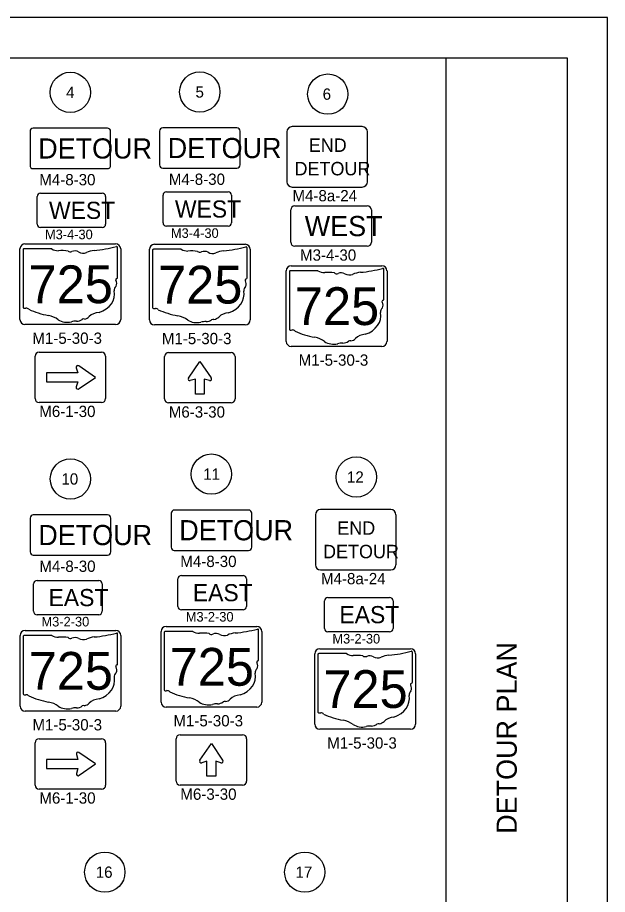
# Model space of a CAD drawing. Extents: x 1341221 to 1914484, y 79347 to 658398.
# Drawn here: x 1461287 to 1494221, y 609451 to 658398 of the extents above; entities that cross this region are included whole.
import ezdxf

# ---------------------------------------------------------------- set-up
doc = ezdxf.new("R2010")
doc.units = 0
for name, color, linetype in [('GM_X_County', 7, 'Continuous'), ('GM_X_County_Road_Text', 7, 'Continuous'), ('GM_X_Minor_Lake', 7, 'Continuous'), ('GM_X_Minor_Lake_Text', 7, 'Continuous'), ('GM_X_Minor_River', 7, 'Continuous'), ('GM_X_Minor_River_Text', 7, 'Continuous')]:
    doc.layers.add(name, color=color, linetype=linetype)

msp = doc.modelspace()

# ---------------------------------------------------------------- linework, layer by layer
at = {"layer": 'GM_X_County'}
for centre in [(1464234, 654220), (1471463, 654244), (1478606, 654124), (1472109, 632912), (1480199, 632751), (1464239, 632642)]:
    msp.add_circle(centre, 1125, dxfattribs=at)
at = {"layer": 'GM_X_County_Road_Text'}
for centre in [(1466159, 610695), (1477321, 610695)]:
    msp.add_circle(centre, 1125, dxfattribs=at)
at = {"layer": 'GM_X_Minor_Lake_Text'}
msp.add_line((1485221, 561648), (1485221, 656148), dxfattribs=at)
msp.add_lwpolyline([(1347971, 656148), (1491971, 656148), (1491971, 561648), (1347971, 561648)], close=True, dxfattribs=at)
at = {"layer": 'GM_X_Minor_River'}
for p, q in [((1462571, 648594), (1466014, 648594)), ((1469602, 648667), (1473045, 648667)), ((1469602, 648667), (1473045, 648667)), ((1462380, 646873), (1462380, 648403)), ((1466205, 648403), (1466205, 646873)), ((1469411, 646946), (1469411, 648476)), ((1469411, 646946), (1469411, 648476)), ((1473236, 648476), (1473236, 646946)), ((1473236, 648476), (1473236, 646946)), ((1476540, 645858), (1476540, 647658)), ((1476765, 647883), (1480815, 647883)), ((1481040, 647658), (1481040, 645858)), ((1466014, 646682), (1462571, 646682)), ((1473045, 646754), (1469602, 646754)), ((1473045, 646754), (1469602, 646754)), ((1480815, 645633), (1476765, 645633)), ((1461597, 645431), (1461597, 642229)), ((1463193, 645486), (1461649, 645486)), ((1466870, 643890), (1466870, 645565)), ((1468827, 645411), (1468827, 642209)), ((1470423, 645466), (1468879, 645466)), ((1474100, 643870), (1474100, 645545)), ((1476463, 644210), (1476463, 641008)), ((1478059, 644265), (1476515, 644265)), ((1481737, 642670), (1481737, 644344)), ((1466870, 643891), (1466870, 643890)), ((1474099, 643871), (1474100, 643870)), ((1481736, 642670), (1481737, 642670)), ((1462265, 637131), (1462265, 639493)), ((1462490, 639718), (1465978, 639718)), ((1466203, 639493), (1466203, 637131)), ((1469495, 637110), (1469495, 639473)), ((1469720, 639698), (1473207, 639698)), ((1473432, 639473), (1473432, 637110)), ((1464566, 638847), (1464656, 638558)), ((1465640, 638312), (1464709, 638952)), ((1470824, 638274), (1471463, 639206)), ((1471463, 639206), (1472092, 638288)), ((1464656, 638558), (1462898, 638558)), ((1462898, 638558), (1462898, 638066)), ((1464722, 637683), (1465640, 638312)), ((1462898, 638066), (1464656, 638066)), ((1464656, 638066), (1464566, 637777)), ((1471217, 638221), (1470929, 638132)), ((1471217, 637377), (1471217, 638221)), ((1471998, 638132), (1471709, 638221)), ((1471709, 638221), (1471709, 637377)), ((1471709, 637377), (1471217, 637377)), ((1465978, 636906), (1462490, 636906)), ((1473207, 636885), (1469720, 636885)), ((1470241, 625531), (1470241, 627061)), ((1470432, 627252), (1473874, 627252)), ((1474066, 627061), (1474066, 625531)), ((1462185, 625258), (1462185, 626788)), ((1462376, 626979), (1465819, 626979)), ((1466010, 626788), (1466010, 625258)), ((1478424, 624305), (1478424, 625835)), ((1478616, 626026), (1482058, 626026)), ((1482249, 625835), (1482249, 624305)), ((1465819, 625066), (1462376, 625066)), ((1473874, 625340), (1470432, 625340)), ((1471069, 624134), (1469524, 624134)), ((1474746, 622538), (1474746, 624213)), ((1482058, 624114), (1478616, 624114)), ((1461602, 623853), (1461602, 620651)), ((1463198, 623908), (1461654, 623908)), ((1466875, 622313), (1466875, 623988)), ((1469472, 624079), (1469472, 620877)), ((1478056, 622837), (1478056, 619635)), ((1479652, 622892), (1478108, 622892)), ((1483330, 621296), (1483330, 622971)), ((1466875, 622313), (1466875, 622313)), ((1474745, 622538), (1474746, 622538)), ((1483329, 621297), (1483330, 621296)), ((1470365, 618366), (1473853, 618366)), ((1462270, 615553), (1462270, 617916)), ((1462495, 618141), (1465982, 618141)), ((1466207, 617916), (1466207, 615553)), ((1470140, 615778), (1470140, 618141)), ((1471469, 616942), (1472109, 617874)), ((1472109, 617874), (1472738, 616956)), ((1474078, 618141), (1474078, 615778)), ((1464571, 617269), (1464660, 616980)), ((1465645, 616734), (1464714, 617374)), ((1464660, 616980), (1462903, 616980)), ((1462903, 616980), (1462903, 616488)), ((1471863, 616889), (1471574, 616800)), ((1471863, 616045), (1471863, 616889)), ((1472644, 616800), (1472355, 616889)), ((1472355, 616889), (1472355, 616045)), ((1462903, 616488), (1464660, 616488)), ((1464660, 616488), (1464571, 616200)), ((1464727, 616106), (1465645, 616734)), ((1472355, 616045), (1471863, 616045)), ((1465982, 615328), (1462495, 615328)), ((1473853, 615553), (1470365, 615553))]:
    msp.add_line(p, q, dxfattribs=at)
for points in [[(1461984, 652035), (1461984, 650145)], [(1466304, 652215), (1462164, 652215)], [(1466484, 650145), (1466484, 652035)], [(1469213, 652060), (1469213, 650170)], [(1473533, 652240), (1469393, 652240)], [(1473713, 650170), (1473713, 652060)], [(1476323, 652018), (1476323, 649228)], [(1480530, 652310), (1476615, 652310)], [(1480823, 649228), (1480823, 652018)], [(1462164, 649965), (1466304, 649965)], [(1469393, 649990), (1473533, 649990)], [(1476615, 648935), (1480530, 648935)], [(1461703, 645762), (1466765, 645762)], [(1468932, 645742), (1473995, 645742)], [(1461421, 641543), (1461421, 645481)], [(1467046, 645481), (1467046, 641543)], [(1468651, 641523), (1468651, 645461)], [(1474276, 645461), (1474276, 641523)], [(1476288, 640322), (1476288, 644260)], [(1476569, 644541), (1481631, 644541)], [(1481913, 644260), (1481913, 640322)], [(1466765, 641262), (1461703, 641262)], [(1473995, 641242), (1468932, 641242)], [(1481631, 640041), (1476569, 640041)], [(1482123, 630937), (1478208, 630937)], [(1461989, 630458), (1461989, 628568)], [(1466309, 630638), (1462169, 630638)], [(1466489, 628568), (1466489, 630458)], [(1469859, 630727), (1469859, 628837)], [(1474179, 630907), (1470039, 630907)], [(1474359, 628837), (1474359, 630727)], [(1477916, 630645), (1477916, 627855)], [(1482416, 627855), (1482416, 630645)], [(1470039, 628657), (1474179, 628657)], [(1462169, 628388), (1466309, 628388)], [(1478208, 627562), (1482123, 627562)], [(1461707, 624184), (1466770, 624184)], [(1469297, 620191), (1469297, 624128)], [(1469578, 624410), (1474640, 624410)], [(1474922, 624128), (1474922, 620191)], [(1461426, 619966), (1461426, 623903)], [(1467051, 623903), (1467051, 619966)], [(1478162, 623168), (1483224, 623168)], [(1477881, 618949), (1477881, 622887)], [(1483506, 622887), (1483506, 618949)], [(1466770, 619684), (1461707, 619684)], [(1474640, 619910), (1469578, 619910)], [(1483224, 618668), (1478162, 618668)]]:
    msp.add_lwpolyline(points, dxfattribs=at)
for centre, radius, start, end in [((1462164, 652035), 180, 90, 180), ((1466304, 652035), 180, 0, 90), ((1469393, 652060), 180, 90, 180), ((1473533, 652060), 180, 0, 90), ((1476615, 652018), 292, 90, 180), ((1480530, 652018), 292, 0, 90), ((1462164, 650145), 180, 180, 270), ((1466304, 650145), 180, 270, 0), ((1469393, 650170), 180, 180, 270), ((1473533, 650170), 180, 270, 0), ((1476615, 649228), 292, 180, 270), ((1480530, 649228), 292, 270, 0), ((1462571, 648403), 191, 90, 180), ((1466014, 648403), 191, 0, 90), ((1469602, 648476), 191, 90, 180), ((1469602, 648476), 191, 90, 180), ((1473045, 648476), 191, 0, 90), ((1473045, 648476), 191, 0, 90), ((1476765, 647658), 225, 90, 180), ((1480815, 647658), 225, 0, 90), ((1462571, 646873), 191, 180, 270), ((1466014, 646873), 191, 270, 0), ((1469602, 646946), 191, 180, 270), ((1469602, 646946), 191, 180, 270), ((1473045, 646946), 191, 270, 0), ((1473045, 646946), 191, 270, 0), ((1461703, 645481), 281, 90, 180), ((1466765, 645481), 281, 0, 90), ((1468932, 645461), 281, 90, 180), ((1473995, 645461), 281, 0, 90), ((1476765, 645858), 225, 180, 270), ((1480815, 645858), 225, 270, 0), ((1476569, 644260), 281, 90, 180), ((1481631, 644260), 281, 0, 90), ((1461703, 641543), 281, 180, 270), ((1466765, 641543), 281, 270, 0), ((1468932, 641523), 281, 180, 270), ((1473995, 641523), 281, 270, 0), ((1476569, 640322), 281, 180, 270), ((1481631, 640322), 281, 270, 0), ((1462490, 639494), 225, 90, 180), ((1465978, 639494), 225, 0, 90), ((1469720, 639473), 225, 90, 180), ((1473207, 639473), 225, 0, 90), ((1464656, 638875), 93.8, 55.4112, 197.2046), ((1470901, 638221), 93.8, 145.4112, 287.2046), ((1472026, 638221), 93.8, 252.7954, 45.0096), ((1464656, 637750), 93.8, 162.7954, 315.0096), ((1462490, 637131), 225, 180, 270), ((1465978, 637131), 225, 270, 360), ((1469720, 637111), 225, 180, 270), ((1473207, 637111), 225, 270, 0), ((1478208, 630645), 292, 90, 180), ((1482123, 630645), 292, 0, 90), ((1462169, 630458), 180, 90, 180), ((1466309, 630458), 180, 0, 90), ((1470039, 630727), 180, 90, 180), ((1474179, 630727), 180, 0, 90), ((1462169, 628568), 180, 180, 270), ((1466309, 628568), 180, 270, 0), ((1470039, 628837), 180, 180, 270), ((1474179, 628837), 180, 270, 0), ((1478208, 627855), 292, 180, 270), ((1482123, 627855), 292, 270, 0), ((1470432, 627061), 191, 90, 180), ((1473874, 627061), 191, 0, 90), ((1462376, 626787), 191, 90, 180), ((1465818, 626787), 191, 0, 90), ((1478615, 625835), 191, 90, 180), ((1482058, 625835), 191, 0, 90), ((1462376, 625257), 191, 180, 270), ((1465818, 625257), 191, 270, 0), ((1470432, 625531), 191, 180, 270), ((1473874, 625531), 191, 270, 0), ((1461707, 623903), 281, 90, 180), ((1466770, 623903), 281, 0, 90), ((1469578, 624128), 281, 90, 180), ((1474640, 624128), 281, 0, 90), ((1478615, 624305), 191, 180, 270), ((1482058, 624305), 191, 270, 0), ((1478162, 622887), 281, 90, 180), ((1483224, 622887), 281, 0, 90), ((1469578, 620191), 281, 180, 270), ((1474640, 620191), 281, 270, 0), ((1461707, 619966), 281, 180, 270), ((1466770, 619966), 281, 270, 0), ((1478162, 618949), 281, 180, 270), ((1483224, 618949), 281, 270, 0), ((1470365, 618141), 225, 90, 180), ((1473853, 618141), 225, 0, 90), ((1462495, 617916), 225, 90, 180), ((1465982, 617916), 225, 0, 90), ((1464661, 617297), 93.8, 55.4112, 197.2046), ((1471547, 616889), 93.8, 145.4112, 287.2046), ((1472672, 616889), 93.8, 252.7954, 45.0096), ((1464661, 616172), 93.8, 162.7954, 315.0096), ((1470365, 615779), 225, 180, 270), ((1473853, 615779), 225, 270, 0), ((1462495, 615553), 225, 180, 270), ((1465982, 615553), 225, 270, 360)]:
    msp.add_arc(centre, radius, start, end, dxfattribs=at)
for centre, major_axis, start_param, end_param in [((1464992, 649851), (5592, 0), 4.814394, 5.042369), ((1466812, 645572), (58.7, 0), 6.141152, 7.989035), ((1461657, 645438), (61.1, 0), 1.712693, 3.28349), ((1463561, 645858), (593, 0), 4.042523, 4.731795), ((1463757, 643688), (2127, 0), 1.404758, 1.657858), ((1464240, 645454), (171, 0), 3.836095, 5.185415), ((1464491, 645084), (355, 0), 0.950623, 2.079405), ((1464950, 645592), (428, 0), 4.081561, 5.145723), ((1465705, 644508), (1125, 0), 1.699011, 2.107814), ((1468887, 645417), (61.1, 0), 1.712693, 3.28349), ((1470791, 645837), (593, 0), 4.042523, 4.731795), ((1470987, 643668), (2127, 0), 1.404758, 1.657858), ((1471470, 645434), (171, 0), 3.836095, 5.185415), ((1471721, 645064), (355, 0), 0.950623, 2.079405), ((1472180, 645572), (428, 0), 4.081561, 5.145723), ((1472935, 644488), (1125, 0), 1.699011, 2.107814), ((1472222, 649831), (5592, 0), 4.814394, 5.042369), ((1474041, 645552), (58.7, 0), 6.141152, 7.989035), ((1476524, 644217), (61.1, 0), 1.712693, 3.28349), ((1478427, 644637), (593, 0), 4.042523, 4.731795), ((1478624, 642468), (2127, 0), 1.404758, 1.657858), ((1479358, 643863), (355, 0), 0.950623, 2.079405), ((1480571, 643287), (1125, 0), 1.699011, 2.107814), ((1479858, 648630), (5592, 0), 4.814394, 5.042369), ((1481678, 644351), (58.7, 0), 6.141152, 7.989035), ((1466857, 643767), (90.9, 0), 1.883978, 3.671073), ((1466279, 643556), (545, 0), 5.934695, 6.695948), ((1466808, 643884), (62.8, 0), 5.05454, 6.418171), ((1474086, 643747), (90.9, 0), 1.883978, 3.671073), ((1473508, 643535), (545, 0), 5.934695, 6.695948), ((1474037, 643864), (62.8, 0), 5.05454, 6.418171), ((1479107, 644233), (171, 0), 3.836095, 5.185415), ((1479816, 644371), (428, 0), 4.081561, 5.145723), ((1467081, 643190), (397, 0), 2.387724, 3.262537), ((1474310, 643169), (397, 0), 2.387724, 3.262537), ((1465305, 642976), (1399, 0), 5.101752, 6.440018), ((1472535, 642956), (1399, 0), 5.101752, 6.440018), ((1461658, 642222), (61.6, 0), 3.00124, 4.508301), ((1468888, 642202), (61.6, 0), 3.00124, 4.508301), ((1481723, 642547), (90.9, 0), 1.883978, 3.671073), ((1481145, 642335), (545, 0), 5.934695, 6.695948), ((1481674, 642663), (62.8, 0), 5.05454, 6.418171), ((1461667, 642550), (470, 0), 4.665946, 4.897461), ((1461763, 642044), (170, 0), 0.519207, 1.627899), ((1463905, 644921), (4038, 0), 4.195997, 4.488961), ((1462701, 640791), (1264, 0), 0.823519, 1.323587), ((1464924, 641919), (452, 0), 4.937069, 5.64225), ((1465895, 641330), (766, 0), 1.647645, 2.488434), ((1468897, 642529), (470, 0), 4.665946, 4.897461), ((1468993, 642024), (170, 0), 0.519207, 1.627899), ((1471134, 644901), (4038, 0), 4.195997, 4.488961), ((1469930, 640770), (1264, 0), 0.823519, 1.323587), ((1473125, 641310), (766, 0), 1.647645, 2.488434), ((1480171, 641755), (1399, 0), 5.101752, 6.440018), ((1481947, 641969), (397, 0), 2.387724, 3.262537), ((1464067, 642028), (802, 0), 4.026481, 4.996735), ((1464531, 640921), (659, 0), 1.495662, 1.94098), ((1464589, 641789), (427, 0), 4.691044, 5.507374), ((1464976, 641479), (120, 0), 1.147584, 2.315152), ((1471297, 642008), (802, 0), 4.026481, 4.996735), ((1471760, 640901), (659, 0), 1.495662, 1.94098), ((1471819, 641768), (427, 0), 4.691044, 5.507374), ((1472205, 641458), (120, 0), 1.147584, 2.315152), ((1472154, 641898), (452, 0), 4.937069, 5.64225), ((1476524, 641001), (61.6, 0), 3.00124, 4.508301), ((1476534, 641329), (470, 0), 4.665946, 4.897461), ((1476630, 640823), (170, 0), 0.519207, 1.627899), ((1478771, 643700), (4038, 0), 4.195997, 4.488961), ((1477567, 639570), (1264, 0), 0.823519, 1.323587), ((1478934, 640807), (802, 0), 4.026481, 4.996735), ((1479397, 639700), (659, 0), 1.495662, 1.94098), ((1479455, 640568), (427, 0), 4.691044, 5.507374), ((1479842, 640258), (120, 0), 1.147584, 2.315152), ((1479791, 640698), (452, 0), 4.937069, 5.64225), ((1480761, 640109), (766, 0), 1.647645, 2.488434), ((1469533, 624085), (61.1, 0), 1.712693, 3.28349), ((1471436, 624505), (593, 0), 4.042523, 4.731795), ((1472867, 628499), (5592, 0), 4.814394, 5.042369), ((1474687, 624220), (58.7, 0), 6.141152, 7.989035), ((1461662, 623860), (61.1, 0), 1.712693, 3.28349), ((1463566, 624280), (593, 0), 4.042523, 4.731795), ((1463762, 622111), (2127, 0), 1.404758, 1.657858), ((1464245, 623877), (171, 0), 3.836095, 5.185415), ((1464496, 623507), (355, 0), 0.950623, 2.079405), ((1464955, 624014), (428, 0), 4.081561, 5.145723), ((1465710, 622930), (1125, 0), 1.699011, 2.107814), ((1464997, 628274), (5592, 0), 4.814394, 5.042369), ((1466817, 623995), (58.7, 0), 6.141152, 7.989035), ((1471633, 622336), (2127, 0), 1.404758, 1.657858), ((1472116, 624102), (171, 0), 3.836095, 5.185415), ((1472367, 623732), (355, 0), 0.950623, 2.079405), ((1472825, 624239), (428, 0), 4.081561, 5.145723), ((1473581, 623156), (1125, 0), 1.699011, 2.107814), ((1478117, 622844), (61.1, 0), 1.712693, 3.28349), ((1480020, 623264), (593, 0), 4.042523, 4.731795), ((1480217, 621094), (2127, 0), 1.404758, 1.657858), ((1480700, 622860), (171, 0), 3.836095, 5.185415), ((1480951, 622490), (355, 0), 0.950623, 2.079405), ((1481409, 622998), (428, 0), 4.081561, 5.145723), ((1482164, 621914), (1125, 0), 1.699011, 2.107814), ((1481451, 627257), (5592, 0), 4.814394, 5.042369), ((1483271, 622978), (58.7, 0), 6.141152, 7.989035), ((1466861, 622190), (90.9, 0), 1.883978, 3.671073), ((1466283, 621978), (545, 0), 5.934695, 6.695948), ((1466812, 622306), (62.8, 0), 5.05454, 6.418171), ((1474732, 622415), (90.9, 0), 1.883978, 3.671073), ((1474154, 622203), (545, 0), 5.934695, 6.695948), ((1474683, 622532), (62.8, 0), 5.05454, 6.418171), ((1467085, 621612), (397, 0), 2.387724, 3.262537), ((1473180, 621624), (1399, 0), 5.101752, 6.440018), ((1474956, 621837), (397, 0), 2.387724, 3.262537), ((1465310, 621399), (1399, 0), 5.101752, 6.440018), ((1483316, 621173), (90.9, 0), 1.883978, 3.671073), ((1483267, 621290), (62.8, 0), 5.05454, 6.418171), ((1469533, 620870), (61.6, 0), 3.00124, 4.508301), ((1469543, 621197), (470, 0), 4.665946, 4.897461), ((1469639, 620692), (170, 0), 0.519207, 1.627899), ((1471780, 623569), (4038, 0), 4.195997, 4.488961), ((1483540, 620595), (397, 0), 2.387724, 3.262537), ((1482738, 620962), (545, 0), 5.934695, 6.695948), ((1461663, 620644), (61.6, 0), 3.00124, 4.508301), ((1461672, 620972), (470, 0), 4.665946, 4.897461), ((1461768, 620467), (170, 0), 0.519207, 1.627899), ((1463909, 623343), (4038, 0), 4.195997, 4.488961), ((1462705, 619213), (1264, 0), 0.823519, 1.323587), ((1465900, 619752), (766, 0), 1.647645, 2.488434), ((1470576, 619438), (1264, 0), 0.823519, 1.323587), ((1471943, 620676), (802, 0), 4.026481, 4.996735), ((1472464, 620436), (427, 0), 4.691044, 5.507374), ((1472851, 620126), (120, 0), 1.147584, 2.315152), ((1472800, 620566), (452, 0), 4.937069, 5.64225), ((1473770, 619978), (766, 0), 1.647645, 2.488434), ((1481764, 620382), (1399, 0), 5.101752, 6.440018), ((1464072, 620451), (802, 0), 4.026481, 4.996735), ((1464535, 619344), (659, 0), 1.495662, 1.94098), ((1464594, 620211), (427, 0), 4.691044, 5.507374), ((1464980, 619901), (120, 0), 1.147584, 2.315152), ((1464929, 620341), (452, 0), 4.937069, 5.64225), ((1472406, 619569), (659, 0), 1.495662, 1.94098), ((1478117, 619628), (61.6, 0), 3.00124, 4.508301), ((1478127, 619955), (470, 0), 4.665946, 4.897461), ((1478223, 619450), (170, 0), 0.519207, 1.627899), ((1480364, 622327), (4038, 0), 4.195997, 4.488961), ((1482354, 618736), (766, 0), 1.647645, 2.488434), ((1479160, 618196), (1264, 0), 0.823519, 1.323587), ((1480527, 619434), (802, 0), 4.026481, 4.996735), ((1480990, 618327), (659, 0), 1.495662, 1.94098), ((1481048, 619195), (427, 0), 4.691044, 5.507374), ((1481435, 618884), (120, 0), 1.147584, 2.315152), ((1481384, 619325), (452, 0), 4.937069, 5.64225)]:
    msp.add_ellipse(centre, major_axis=major_axis, ratio=0.8, start_param=start_param, end_param=end_param, dxfattribs=at)
at = {"layer": 'GM_X_Minor_River_Text'}
msp.add_lwpolyline([(1341221, 559398), (1494221, 559398), (1494221, 658398), (1341221, 658398)], close=True, dxfattribs=at)

# ---------------------------------------------------------------- texts
at = {"layer": 'GM_X_County'}
for s, p in [('4', (1464000, 653905)), ('5', (1471223, 653929)), ('6', (1478321, 653809)), ('10', (1463737, 632327)), ('11', (1471652, 632597)), ('12', (1479680, 632436))]:
    msp.add_text(s, height=630, dxfattribs=at).set_placement(p)
at = {"layer": 'GM_X_County_Road_Text'}
for s, height, p in [('M4-8-30', 630, (1462501, 649034)), ('M4-8-30', 630, (1469731, 649058)), ('M4-8a-24', 630, (1476636, 648139)), ('M3-4-30', 535.5, (1469850, 646098)), ('M3-4-30', 535.5, (1469850, 646098)), ('M3-4-30', 535.5, (1462819, 646025)), ('M3-4-30', 630, (1477057, 644827)), ('M1-5-30-3', 630, (1462114, 640185)), ('M1-5-30-3', 630, (1469344, 640165)), ('M1-5-30-3', 630, (1476981, 638964)), ('M6-1-30', 630, (1462501, 636099)), ('M6-3-30', 630, (1469731, 636068)), ('M4-8-30', 630, (1462506, 627456)), ('M4-8-30', 630, (1470376, 627726)), ('M4-8a-24', 630, (1478229, 626766)), ('M3-2-30', 535.5, (1470680, 624683)), ('M3-2-30', 535.5, (1462624, 624410)), ('M3-2-30', 535.5, (1478864, 623457)), ('M1-5-30-3', 630, (1462119, 618608)), ('M1-5-30-3', 630, (1469990, 618833)), ('M1-5-30-3', 630, (1478574, 617591)), ('M6-3-30', 630, (1470376, 614736)), ('M6-1-30', 630, (1462506, 614521)), ('16', 630, (1465655, 610380)), ('17', 630, (1476804, 610380))]:
    msp.add_text(s, height=height, dxfattribs=at).set_placement(p)
at = {"layer": 'GM_X_Minor_Lake'}
msp.add_text('DETOUR PLAN', height=1125, rotation=90, dxfattribs=at).set_placement((1489158, 612836))
at = {"layer": 'GM_X_Minor_River'}
for s, height, p in [('DETOUR', 1125, (1462441, 650528)), ('DETOUR', 1125, (1469671, 650552)), ('END', 750, (1477546, 650900)), ('DETOUR', 750, (1476750, 649590)), ('WEST', 956.2, (1463044, 647160)), ('WEST', 956.2, (1470075, 647233)), ('WEST', 956.2, (1470075, 647233)), ('WEST', 1125, (1477322, 646196)), ('725', 2109.4, (1461903, 642455)), ('725', 2109.4, (1469132, 642434)), ('725', 2109.4, (1476769, 641234)), ('DETOUR', 1125, (1462446, 628950)), ('DETOUR', 1125, (1470316, 629220)), ('END', 750, (1479139, 629526)), ('DETOUR', 750, (1478343, 628217)), ('EAST', 956.2, (1471074, 625818)), ('EAST', 956.2, (1463019, 625544)), ('EAST', 956.2, (1479258, 624592)), ('725', 2109.4, (1469778, 621102)), ('725', 2109.4, (1461907, 620877)), ('725', 2109.4, (1478362, 619861))]:
    msp.add_text(s, height=height, dxfattribs=at).set_placement(p)

doc.saveas('drawing.dxf')
